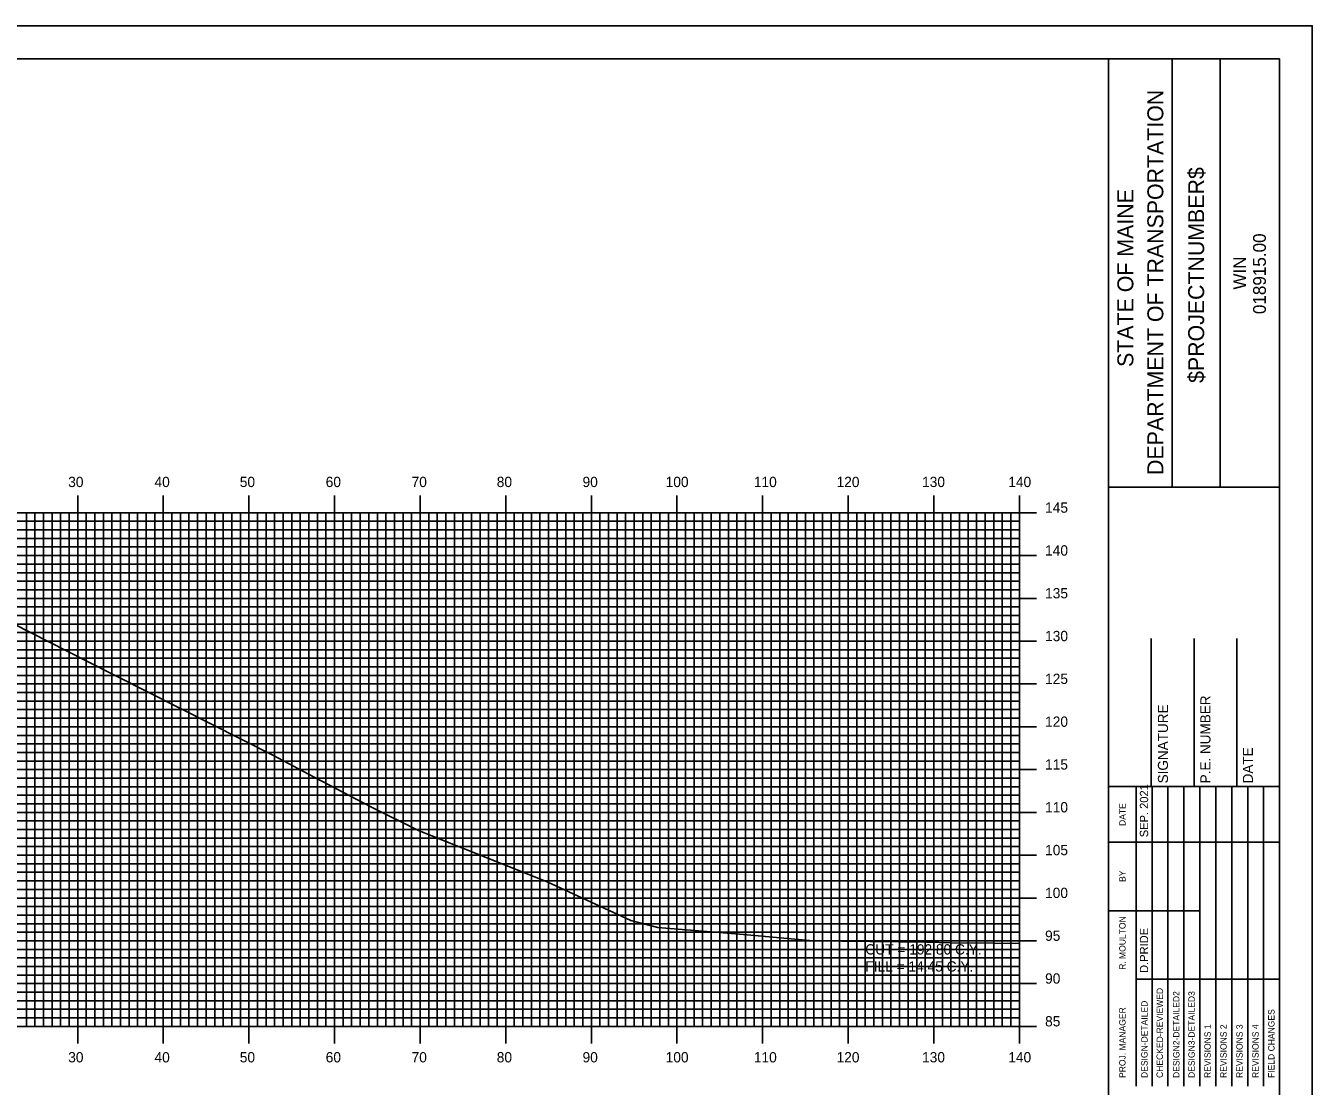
# Model space of a CAD drawing. Extents: x 859865 to 860208, y 364765 to 364985.
# Drawn here: x 860054.3 to 860204.6, y 364861.3 to 364985.2 of the extents above; entities that cross this region are included whole.
import ezdxf

# ---------------------------------------------------------------- set-up
doc = ezdxf.new("R2010")
doc.units = 0
for name, color, linetype in [('BORDER', 7, 'Continuous'), ('D_Text_Standard', 7, 'Continuous'), ('H_V ANNOTATION', 7, 'Continuous'), ('MAJOR', 7, 'Continuous'), ('MINOR', 7, 'Continuous'), ('PLOT BOUNDARY', 7, 'Continuous'), ('S_Roadway_Centerline', 7, 'Continuous')]:
    doc.layers.add(name, color=color, linetype=linetype)

msp = doc.modelspace()

# ---------------------------------------------------------------- linework, layer by layer
at = {"layer": 'BORDER'}
for p, q in [((860180.79, 364771.3), (860180.79, 364981.3)), ((860188.24, 364931.3), (860188.24, 364981.3)), ((860193.83, 364931.3), (860193.83, 364981.3)), ((860180.79, 364931.29), (860200.79, 364931.29)), ((860185.79, 364896.31), (860185.79, 364913.6)), ((860190.79, 364896.31), (860190.79, 364913.6)), ((860195.79, 364896.31), (860195.79, 364913.6)), ((860180.79, 364896.31), (860200.79, 364896.31))]:
    msp.add_line(p, q, dxfattribs=at)
msp.add_lwpolyline([(859880.79, 364771.3), (860200.79, 364771.3), (860200.79, 364981.3), (859880.79, 364981.3)], close=True, dxfattribs=at)
for points in [[(860184.02, 364889.81), (860184.02, 364896.31)], [(860185.88, 364861.31), (860185.88, 364896.31)], [(860187.74, 364896.31), (860187.74, 364861.31)], [(860189.61, 364861.31), (860189.61, 364896.31)], [(860191.47, 364861.31), (860191.47, 364896.31)], [(860193.33, 364861.31), (860193.33, 364896.31)], [(860195.2, 364861.31), (860195.2, 364896.31)], [(860197.06, 364861.31), (860197.06, 364896.31)], [(860198.92, 364861.31), (860198.92, 364896.31)], [(860184.02, 364861.31), (860184.02, 364894.9)], [(860180.79, 364889.81), (860200.79, 364889.81)], [(860180.79, 364881.81), (860184.02, 364881.81)], [(860184.02, 364881.81), (860191.47, 364881.81)], [(860184.02, 364873.81), (860200.79, 364873.81)]]:
    msp.add_lwpolyline(points, dxfattribs=at)
at = {"layer": 'MAJOR'}
for p, q in [((860060.39, 364930.31), (860060.39, 364928.3)), ((860070.39, 364930.31), (860070.39, 364928.3)), ((860080.39, 364930.31), (860080.39, 364928.3)), ((860090.39, 364930.31), (860090.39, 364928.3)), ((860100.39, 364930.31), (860100.39, 364928.3)), ((860110.39, 364930.31), (860110.39, 364928.3)), ((860120.39, 364930.31), (860120.39, 364928.3)), ((860130.39, 364930.31), (860130.39, 364928.3)), ((860140.39, 364930.31), (860140.39, 364928.3)), ((860150.39, 364930.31), (860150.39, 364928.3)), ((860160.39, 364930.31), (860160.39, 364928.3)), ((860170.39, 364930.31), (860170.39, 364928.3)), ((859890.39, 364928.3), (860170.39, 364928.3)), ((859890.39, 364928.3), (860170.39, 364928.3)), ((860060.39, 364868.3), (860060.39, 364928.3)), ((860070.39, 364868.3), (860070.39, 364928.3)), ((860080.39, 364868.3), (860080.39, 364928.3)), ((860090.39, 364868.3), (860090.39, 364928.3)), ((860100.39, 364868.3), (860100.39, 364928.3)), ((860110.39, 364868.3), (860110.39, 364928.3)), ((860120.39, 364868.3), (860120.39, 364928.3)), ((860130.39, 364868.3), (860130.39, 364928.3)), ((860140.39, 364868.3), (860140.39, 364928.3)), ((860150.39, 364868.3), (860150.39, 364928.3)), ((860160.39, 364868.3), (860160.39, 364928.3)), ((860172.39, 364928.3), (860168.38, 364928.3)), ((860170.39, 364868.3), (860170.39, 364928.3)), ((860170.39, 364868.3), (860170.39, 364928.3)), ((859890.39, 364923.3), (860170.39, 364923.3)), ((860172.39, 364923.3), (860168.38, 364923.3)), ((859890.39, 364918.3), (860170.39, 364918.3)), ((860172.39, 364918.3), (860168.38, 364918.3)), ((859890.39, 364913.3), (860170.39, 364913.3)), ((860172.39, 364913.3), (860168.38, 364913.3)), ((859890.39, 364908.3), (860170.39, 364908.3)), ((860172.39, 364908.3), (860168.38, 364908.3)), ((859890.39, 364903.3), (860170.39, 364903.3)), ((860172.39, 364903.3), (860168.38, 364903.3)), ((859890.39, 364898.3), (860170.39, 364898.3)), ((860172.39, 364898.3), (860168.38, 364898.3)), ((859890.39, 364893.3), (860170.39, 364893.3)), ((860172.39, 364893.3), (860168.38, 364893.3)), ((859890.39, 364888.3), (860170.39, 364888.3)), ((860172.39, 364888.3), (860168.38, 364888.3)), ((859890.39, 364883.3), (860170.39, 364883.3)), ((860172.39, 364883.3), (860168.38, 364883.3)), ((859890.39, 364878.3), (860170.39, 364878.3)), ((860172.39, 364878.3), (860168.38, 364878.3)), ((859890.39, 364873.3), (860170.39, 364873.3)), ((860172.39, 364873.3), (860168.38, 364873.3)), ((859890.39, 364868.3), (860170.39, 364868.3)), ((859890.39, 364868.3), (860170.39, 364868.3)), ((860060.39, 364866.3), (860060.39, 364868.3)), ((860070.39, 364866.3), (860070.39, 364868.3)), ((860080.39, 364866.3), (860080.39, 364868.3)), ((860090.39, 364866.3), (860090.39, 364868.3)), ((860100.39, 364866.3), (860100.39, 364868.3)), ((860110.39, 364866.3), (860110.39, 364868.3)), ((860120.39, 364866.3), (860120.39, 364868.3)), ((860130.39, 364866.3), (860130.39, 364868.3)), ((860140.39, 364866.3), (860140.39, 364868.3)), ((860150.39, 364866.3), (860150.39, 364868.3)), ((860160.39, 364866.3), (860160.39, 364868.3)), ((860172.39, 364868.3), (860168.38, 364868.3)), ((860170.39, 364866.3), (860170.39, 364868.3))]:
    msp.add_line(p, q, dxfattribs=at)
at = {"layer": 'MINOR'}
for p, q in [((859890.39, 364927.3), (860170.39, 364927.3)), ((860054.39, 364868.3), (860054.39, 364928.3)), ((860055.39, 364868.3), (860055.39, 364928.3)), ((860056.39, 364868.3), (860056.39, 364928.3)), ((860057.39, 364868.3), (860057.39, 364928.3)), ((860058.39, 364868.3), (860058.39, 364928.3)), ((860059.39, 364868.3), (860059.39, 364928.3)), ((860061.39, 364868.3), (860061.39, 364928.3)), ((860062.39, 364868.3), (860062.39, 364928.3)), ((860063.39, 364868.3), (860063.39, 364928.3)), ((860064.39, 364868.3), (860064.39, 364928.3)), ((860065.39, 364868.3), (860065.39, 364928.3)), ((860066.39, 364868.3), (860066.39, 364928.3)), ((860067.39, 364868.3), (860067.39, 364928.3)), ((860068.39, 364868.3), (860068.39, 364928.3)), ((860069.39, 364868.3), (860069.39, 364928.3)), ((860071.39, 364868.3), (860071.39, 364928.3)), ((860072.39, 364868.3), (860072.39, 364928.3)), ((860073.39, 364868.3), (860073.39, 364928.3)), ((860074.39, 364868.3), (860074.39, 364928.3)), ((860075.39, 364868.3), (860075.39, 364928.3)), ((860076.39, 364868.3), (860076.39, 364928.3)), ((860077.39, 364868.3), (860077.39, 364928.3)), ((860078.39, 364868.3), (860078.39, 364928.3)), ((860079.39, 364868.3), (860079.39, 364928.3)), ((860081.39, 364868.3), (860081.39, 364928.3)), ((860082.39, 364868.3), (860082.39, 364928.3)), ((860083.39, 364868.3), (860083.39, 364928.3)), ((860084.39, 364868.3), (860084.39, 364928.3)), ((860085.39, 364868.3), (860085.39, 364928.3)), ((860086.39, 364868.3), (860086.39, 364928.3)), ((860087.39, 364868.3), (860087.39, 364928.3)), ((860088.39, 364868.3), (860088.39, 364928.3)), ((860089.39, 364868.3), (860089.39, 364928.3)), ((860091.39, 364868.3), (860091.39, 364928.3)), ((860092.39, 364868.3), (860092.39, 364928.3)), ((860093.39, 364868.3), (860093.39, 364928.3)), ((860094.39, 364868.3), (860094.39, 364928.3)), ((860095.39, 364868.3), (860095.39, 364928.3)), ((860096.39, 364868.3), (860096.39, 364928.3)), ((860097.39, 364868.3), (860097.39, 364928.3)), ((860098.39, 364868.3), (860098.39, 364928.3)), ((860099.39, 364868.3), (860099.39, 364928.3)), ((860101.39, 364868.3), (860101.39, 364928.3)), ((860102.39, 364868.3), (860102.39, 364928.3)), ((860103.39, 364868.3), (860103.39, 364928.3)), ((860104.39, 364868.3), (860104.39, 364928.3)), ((860105.39, 364868.3), (860105.39, 364928.3)), ((860106.39, 364868.3), (860106.39, 364928.3)), ((860107.39, 364868.3), (860107.39, 364928.3)), ((860108.39, 364868.3), (860108.39, 364928.3)), ((860109.39, 364868.3), (860109.39, 364928.3)), ((860111.39, 364868.3), (860111.39, 364928.3)), ((860112.39, 364868.3), (860112.39, 364928.3)), ((860113.39, 364868.3), (860113.39, 364928.3)), ((860114.39, 364868.3), (860114.39, 364928.3)), ((860115.39, 364868.3), (860115.39, 364928.3)), ((860116.39, 364868.3), (860116.39, 364928.3)), ((860117.39, 364868.3), (860117.39, 364928.3)), ((860118.39, 364868.3), (860118.39, 364928.3)), ((860119.39, 364868.3), (860119.39, 364928.3)), ((860121.39, 364868.3), (860121.39, 364928.3)), ((860122.39, 364868.3), (860122.39, 364928.3)), ((860123.39, 364868.3), (860123.39, 364928.3)), ((860124.39, 364868.3), (860124.39, 364928.3)), ((860125.39, 364868.3), (860125.39, 364928.3)), ((860126.39, 364868.3), (860126.39, 364928.3)), ((860127.39, 364868.3), (860127.39, 364928.3)), ((860128.39, 364868.3), (860128.39, 364928.3)), ((860129.39, 364868.3), (860129.39, 364928.3)), ((860131.39, 364868.3), (860131.39, 364928.3)), ((860132.39, 364868.3), (860132.39, 364928.3)), ((860133.39, 364868.3), (860133.39, 364928.3)), ((860134.39, 364868.3), (860134.39, 364928.3)), ((860135.39, 364868.3), (860135.39, 364928.3)), ((860136.39, 364868.3), (860136.39, 364928.3)), ((860137.39, 364868.3), (860137.39, 364928.3)), ((860138.39, 364868.3), (860138.39, 364928.3)), ((860139.39, 364868.3), (860139.39, 364928.3)), ((860141.39, 364868.3), (860141.39, 364928.3)), ((860142.39, 364868.3), (860142.39, 364928.3)), ((860143.39, 364868.3), (860143.39, 364928.3)), ((860144.39, 364868.3), (860144.39, 364928.3)), ((860145.39, 364868.3), (860145.39, 364928.3)), ((860146.39, 364868.3), (860146.39, 364928.3)), ((860147.39, 364868.3), (860147.39, 364928.3)), ((860148.39, 364868.3), (860148.39, 364928.3)), ((860149.39, 364868.3), (860149.39, 364928.3)), ((860151.39, 364868.3), (860151.39, 364928.3)), ((860152.39, 364868.3), (860152.39, 364928.3)), ((860153.39, 364868.3), (860153.39, 364928.3)), ((860154.39, 364868.3), (860154.39, 364928.3)), ((860155.39, 364868.3), (860155.39, 364928.3)), ((860156.39, 364868.3), (860156.39, 364928.3)), ((860157.39, 364868.3), (860157.39, 364928.3)), ((860158.39, 364868.3), (860158.39, 364928.3)), ((860159.39, 364868.3), (860159.39, 364928.3)), ((860161.39, 364868.3), (860161.39, 364928.3)), ((860162.39, 364868.3), (860162.39, 364928.3)), ((860163.39, 364868.3), (860163.39, 364928.3)), ((860164.39, 364868.3), (860164.39, 364928.3)), ((860165.39, 364868.3), (860165.39, 364928.3)), ((860166.39, 364868.3), (860166.39, 364928.3)), ((860167.39, 364868.3), (860167.39, 364928.3)), ((860170.39, 364927.3), (860168.38, 364927.3)), ((860168.39, 364868.3), (860168.39, 364928.3)), ((860169.39, 364868.3), (860169.39, 364928.3)), ((859890.39, 364926.3), (860170.39, 364926.3)), ((860170.39, 364926.3), (860168.38, 364926.3)), ((859890.39, 364925.3), (860170.39, 364925.3)), ((859890.39, 364924.3), (860170.39, 364924.3)), ((860170.39, 364925.3), (860168.38, 364925.3)), ((860170.39, 364924.3), (860168.38, 364924.3)), ((859890.39, 364922.3), (860170.39, 364922.3)), ((859890.39, 364921.3), (860170.39, 364921.3)), ((860170.39, 364922.3), (860168.38, 364922.3)), ((860170.39, 364921.3), (860168.38, 364921.3)), ((859890.39, 364920.3), (860170.39, 364920.3)), ((860170.39, 364920.3), (860168.38, 364920.3)), ((859890.39, 364919.3), (860170.39, 364919.3)), ((860170.39, 364919.3), (860168.38, 364919.3)), ((859890.39, 364917.3), (860170.39, 364917.3)), ((860170.39, 364917.3), (860168.38, 364917.3)), ((859890.39, 364916.3), (860170.39, 364916.3)), ((859890.39, 364915.3), (860170.39, 364915.3)), ((860170.39, 364916.3), (860168.38, 364916.3)), ((860170.39, 364915.3), (860168.38, 364915.3)), ((859890.39, 364914.3), (860170.39, 364914.3)), ((860170.39, 364914.3), (860168.38, 364914.3)), ((859890.39, 364912.3), (860170.39, 364912.3)), ((860170.39, 364912.3), (860168.38, 364912.3)), ((859890.39, 364911.3), (860170.39, 364911.3)), ((860170.39, 364911.3), (860168.38, 364911.3)), ((859890.39, 364910.3), (860170.39, 364910.3)), ((859890.39, 364909.3), (860170.39, 364909.3)), ((860170.39, 364910.3), (860168.38, 364910.3)), ((860170.39, 364909.3), (860168.38, 364909.3)), ((859890.39, 364907.3), (860170.39, 364907.3)), ((859890.39, 364906.3), (860170.39, 364906.3)), ((860170.39, 364907.3), (860168.38, 364907.3)), ((860170.39, 364906.3), (860168.38, 364906.3)), ((859890.39, 364905.3), (860170.39, 364905.3)), ((860170.39, 364905.3), (860168.38, 364905.3)), ((859890.39, 364904.3), (860170.39, 364904.3)), ((860170.39, 364904.3), (860168.38, 364904.3)), ((859890.39, 364902.3), (860170.39, 364902.3)), ((860170.39, 364902.3), (860168.38, 364902.3)), ((859890.39, 364901.3), (860170.39, 364901.3)), ((859890.39, 364900.3), (860170.39, 364900.3)), ((860170.39, 364901.3), (860168.38, 364901.3)), ((860170.39, 364900.3), (860168.38, 364900.3)), ((859890.39, 364899.3), (860170.39, 364899.3)), ((860170.39, 364899.3), (860168.38, 364899.3)), ((859890.39, 364897.3), (860170.39, 364897.3)), ((860170.39, 364897.3), (860168.38, 364897.3)), ((859890.39, 364896.3), (860170.39, 364896.3)), ((860170.39, 364896.3), (860168.38, 364896.3)), ((859890.39, 364895.3), (860170.39, 364895.3)), ((859890.39, 364894.3), (860170.39, 364894.3)), ((860170.39, 364895.3), (860168.38, 364895.3)), ((860170.39, 364894.3), (860168.38, 364894.3)), ((859890.39, 364892.3), (860170.39, 364892.3)), ((859890.39, 364891.3), (860170.39, 364891.3)), ((860170.39, 364892.3), (860168.38, 364892.3)), ((860170.39, 364891.3), (860168.38, 364891.3)), ((859890.39, 364890.3), (860170.39, 364890.3)), ((860170.39, 364890.3), (860168.38, 364890.3)), ((859890.39, 364889.3), (860170.39, 364889.3)), ((860170.39, 364889.3), (860168.38, 364889.3)), ((859890.39, 364887.3), (860170.39, 364887.3)), ((860170.39, 364887.3), (860168.38, 364887.3)), ((859890.39, 364886.3), (860170.39, 364886.3)), ((859890.39, 364885.3), (860170.39, 364885.3)), ((860170.39, 364886.3), (860168.38, 364886.3)), ((860170.39, 364885.3), (860168.38, 364885.3)), ((859890.39, 364884.3), (860170.39, 364884.3)), ((860170.39, 364884.3), (860168.38, 364884.3)), ((859890.39, 364882.3), (860170.39, 364882.3)), ((860170.39, 364882.3), (860168.38, 364882.3)), ((859890.39, 364881.3), (860170.39, 364881.3)), ((860170.39, 364881.3), (860168.38, 364881.3)), ((859890.39, 364880.3), (860170.39, 364880.3)), ((859890.39, 364879.3), (860170.39, 364879.3)), ((860170.39, 364880.3), (860168.38, 364880.3)), ((860170.39, 364879.3), (860168.38, 364879.3)), ((859890.39, 364877.3), (860170.39, 364877.3)), ((859890.39, 364876.3), (860170.39, 364876.3)), ((860170.39, 364877.3), (860168.38, 364877.3)), ((860170.39, 364876.3), (860168.38, 364876.3)), ((859890.39, 364875.3), (860170.39, 364875.3)), ((860170.39, 364875.3), (860168.38, 364875.3)), ((859890.39, 364874.3), (860170.39, 364874.3)), ((860170.39, 364874.3), (860168.38, 364874.3)), ((859890.39, 364872.3), (860170.39, 364872.3)), ((860170.39, 364872.3), (860168.38, 364872.3)), ((859890.39, 364871.3), (860170.39, 364871.3)), ((859890.39, 364870.3), (860170.39, 364870.3)), ((860170.39, 364871.3), (860168.38, 364871.3)), ((860170.39, 364870.3), (860168.38, 364870.3)), ((859890.39, 364869.3), (860170.39, 364869.3)), ((860170.39, 364869.3), (860168.38, 364869.3))]:
    msp.add_line(p, q, dxfattribs=at)
at = {"layer": 'PLOT BOUNDARY'}
msp.add_lwpolyline([(859864.6, 364765.18), (860204.6, 364765.18), (860204.6, 364985.18), (859864.6, 364985.18)], close=True, dxfattribs=at)
at = {"layer": 'S_Roadway_Centerline'}
msp.add_lwpolyline([(860042.21, 364920.74), (860061.3, 364911.05), (860083.25, 364899.96), (860087.36, 364897.76), (860094.71, 364893.93), (860100.28, 364891.13), (860115.22, 364885.19), (860125.01, 364880.68), (860128.15, 364879.87), (860138.18, 364879.05), (860146.29, 364878.28), (860159.59, 364878.16), (860162.42, 364878.07), (860167.38, 364878.03), (860170.39, 364877.97)], dxfattribs=at)

# ---------------------------------------------------------------- texts
at = {"layer": 'BORDER'}
for s, height, p in [('DEPARTMENT OF TRANSPORTATION', 1.8635, (860187.2, 364932.71)), ('$PROJECTNUMBER$', 1.8635, (860191.97, 364943.46)), ('STATE OF MAINE', 1.8635, (860183.7, 364945.33)), ('018915.00', 1.491, (860199.18, 364951.5)), ('WIN', 1.491, (860196.86, 364954.36)), ('P.E. NUMBER', 1.1811, (860192.71, 364896.69)), ('SIGNATURE', 1.181, (860187.75, 364896.69)), ('DATE', 1.181, (860197.67, 364896.69)), ('SEP. 2021', 0.969, (860185.43, 364890.4)), ('DATE', 0.743, (860182.79, 364891.72)), ('BY', 0.743, (860182.79, 364885.18)), ('R. MOULTON', 0.745, (860182.79, 364874.91)), ('D.PRIDE', 0.969, (860185.43, 364874.55)), ('CHECKED-REVIEWED', 0.7455, (860187.15, 364862.28)), ('DESIGN2-DETAILED2', 0.7455, (860189.09, 364862.28)), ('DESIGN3-DETAILED3', 0.7455, (860190.87, 364862.28)), ('PROJ. MANAGER', 0.7455, (860182.79, 364862.28)), ('DESIGN-DETAILED', 0.7455, (860185.36, 364862.28)), ('FIELD CHANGES', 0.7455, (860200.19, 364862.28)), ('REVISIONS 1', 0.7455, (860192.74, 364862.28)), ('REVISIONS 2', 0.7455, (860194.6, 364862.28)), ('REVISIONS 3', 0.7455, (860196.47, 364862.28)), ('REVISIONS 4', 0.7455, (860198.33, 364862.28))]:
    msp.add_text(s, height=height, rotation=90, dxfattribs=at).set_placement(p)
at = {"layer": 'D_Text_Standard'}
for s, p in [('CUT = 192.80 C.Y.', (860152.39, 364876.7)), ('FILL = 14.45 C.Y.', (860152.39, 364874.71))]:
    msp.add_text(s, height=1.2, dxfattribs=at).set_placement(p)
at = {"layer": 'H_V ANNOTATION'}
for s, p in [('30', (860059.28, 364931.3)), ('40', (860069.36, 364931.3)), ('50', (860079.32, 364931.3)), ('60', (860089.36, 364931.3)), ('70', (860099.39, 364931.3)), ('80', (860109.34, 364931.3)), ('90', (860119.36, 364931.3)), ('100', (860129.07, 364931.3)), ('110', (860139.37, 364931.3)), ('120', (860149.03, 364931.3)), ('130', (860159.02, 364931.3)), ('140', (860169.09, 364931.3)), ('145', (860173.39, 364928.3)), ('140', (860173.39, 364923.3)), ('135', (860173.39, 364918.3)), ('130', (860173.39, 364913.3)), ('125', (860173.39, 364908.3)), ('120', (860173.39, 364903.3)), ('115', (860173.39, 364898.3)), ('110', (860173.39, 364893.3)), ('105', (860173.39, 364888.3)), ('100', (860173.39, 364883.3)), ('95', (860173.39, 364878.3)), ('90', (860173.39, 364873.3)), ('85', (860173.39, 364868.3)), ('30', (860059.28, 364864.1)), ('40', (860069.36, 364864.1)), ('50', (860079.32, 364864.1)), ('60', (860089.36, 364864.1)), ('70', (860099.39, 364864.1)), ('80', (860109.34, 364864.1)), ('90', (860119.36, 364864.1)), ('100', (860129.07, 364864.1)), ('110', (860139.37, 364864.1)), ('120', (860149.03, 364864.1)), ('130', (860159.02, 364864.1)), ('140', (860169.09, 364864.1))]:
    msp.add_text(s, height=1.2, dxfattribs=at).set_placement(p)

doc.saveas('drawing.dxf')
